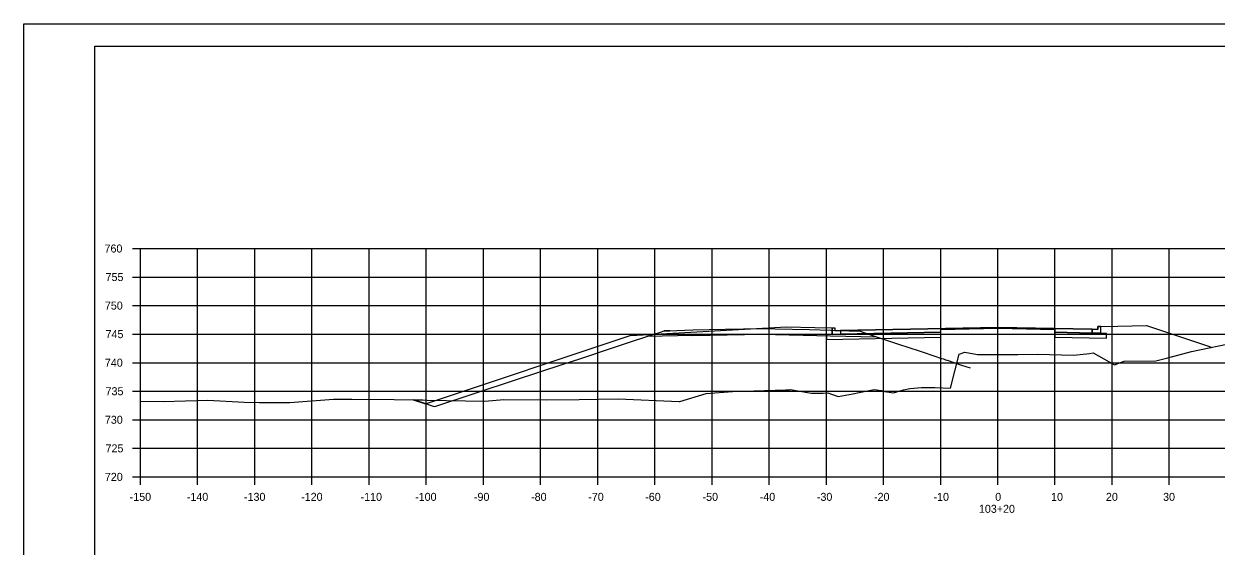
# Model space of a CAD drawing. Extents: x 1202951 to 1376887, y 378065 to 728038.
# Drawn here: x 1374114.6 to 1374323.2, y 378881.8 to 378973.3 of the extents above; entities that cross this region are included whole.
import ezdxf

# ---------------------------------------------------------------- set-up
doc = ezdxf.new("R2010")
doc.units = 0
for name, color, linetype in [('Default', 7, 'Continuous'), ('R_Alt Surface', 7, 'Continuous'), ('R_Axis', 7, 'Continuous'), ('R_Axis Annot', 7, 'Continuous'), ('R_Exist Surface', 7, 'Continuous'), ('R_Fin Surface', 7, 'Continuous'), ('R_Grid', 7, 'Continuous'), ('R_No Plot', 7, 'Continuous'), ('R_Proposed Road', 7, 'Continuous')]:
    doc.layers.add(name, color=color, linetype=linetype)

msp = doc.modelspace()

# ---------------------------------------------------------------- linework, layer by layer
at = {"layer": 'Default'}
for points in [[(1374255.98, 378920.03), (1374256.47, 378920.03), (1374256.48, 378919.53), (1374257.48, 378919.55), (1374257.48, 378918.89), (1374255.98, 378918.86)], [(1374302.98, 378920.25), (1374302.49, 378920.25), (1374302.48, 378919.75), (1374301.48, 378919.77), (1374301.48, 378919.11), (1374302.98, 378919.08)]]:
    msp.add_lwpolyline(points, close=True, dxfattribs=at)
at = {"layer": 'R_Alt Surface'}
for points in [[(1374231.62, 378918.66), (1374243.66, 378918.89), (1374255.71, 378918.63)], [(1374255.98, 378920.03), (1374255.98, 378918.86), (1374257.48, 378918.89), (1374274.98, 378919.24), (1374274.98, 378919.74), (1374284.98, 378919.94), (1374294.98, 378919.74), (1374294.98, 378919.24), (1374301.48, 378919.11), (1374302.98, 378919.08), (1374302.98, 378920.25)], [(1374231.62, 378918.66), (1374223.59, 378918.51)], [(1374255.71, 378918.63), (1374263.75, 378918.46)]]:
    msp.add_lwpolyline(points, dxfattribs=at)
for points in [[(1374257.48, 378918.89), (1374255.98, 378918.86), (1374254.98, 378918.84), (1374254.98, 378918), (1374274.98, 378918.4), (1374274.98, 378919.24)], [(1374257.48, 378919.55), (1374257.48, 378918.89), (1374274.98, 378919.24), (1374274.98, 378919.74), (1374284.98, 378919.94), (1374294.98, 378919.74), (1374294.98, 378919.24), (1374301.48, 378919.11), (1374301.48, 378919.77), (1374301.48, 378919.77), (1374284.98, 378920.1), (1374257.48, 378919.55)], [(1374303.98, 378919.06), (1374302.98, 378919.08), (1374301.48, 378919.11), (1374294.98, 378919.24), (1374294.98, 378918.4), (1374303.98, 378918.22)]]:
    msp.add_lwpolyline(points, close=True, dxfattribs=at)
at = {"layer": 'R_Axis'}
for p, q in [((1374133.58, 378933.92), (1374134.98, 378933.92)), ((1374134.98, 378893.92), (1374134.98, 378933.92)), ((1374133.58, 378928.92), (1374134.98, 378928.92)), ((1374133.58, 378923.92), (1374134.98, 378923.92)), ((1374133.58, 378918.92), (1374134.98, 378918.92)), ((1374133.58, 378913.92), (1374134.98, 378913.92)), ((1374133.58, 378908.92), (1374134.98, 378908.92)), ((1374133.58, 378903.92), (1374134.98, 378903.92)), ((1374133.58, 378898.92), (1374134.98, 378898.92)), ((1374133.58, 378893.92), (1374134.98, 378893.92)), ((1374134.98, 378893.92), (1374434.98, 378893.92)), ((1374134.98, 378892.52), (1374134.98, 378893.92)), ((1374144.98, 378892.52), (1374144.98, 378893.92)), ((1374154.98, 378892.52), (1374154.98, 378893.92)), ((1374164.98, 378892.52), (1374164.98, 378893.92)), ((1374174.98, 378892.52), (1374174.98, 378893.92)), ((1374184.98, 378892.52), (1374184.98, 378893.92)), ((1374194.98, 378892.52), (1374194.98, 378893.92)), ((1374204.98, 378892.52), (1374204.98, 378893.92)), ((1374214.98, 378892.52), (1374214.98, 378893.92)), ((1374224.98, 378892.52), (1374224.98, 378893.92)), ((1374234.98, 378892.52), (1374234.98, 378893.92)), ((1374244.98, 378892.52), (1374244.98, 378893.92)), ((1374254.98, 378892.52), (1374254.98, 378893.92)), ((1374264.98, 378892.52), (1374264.98, 378893.92)), ((1374274.98, 378892.52), (1374274.98, 378893.92)), ((1374284.98, 378892.52), (1374284.98, 378893.92)), ((1374294.98, 378892.52), (1374294.98, 378893.92)), ((1374304.98, 378892.52), (1374304.98, 378893.92)), ((1374314.98, 378892.52), (1374314.98, 378893.92))]:
    msp.add_line(p, q, dxfattribs=at)
at = {"layer": 'R_Exist Surface'}
msp.add_lwpolyline([(1374134.98, 378907.15), (1374138.93, 378907.1), (1374146.74, 378907.35), (1374153.12, 378907), (1374155.78, 378906.94), (1374161.13, 378906.94), (1374168.77, 378907.51), (1374171.95, 378907.54), (1374179.37, 378907.45), (1374183.2, 378907.44), (1374184.38, 378907.44), (1374185.14, 378907.38), (1374195.25, 378907.2), (1374198.54, 378907.45), (1374206.01, 378907.42), (1374211.73, 378907.46), (1374218.53, 378907.56), (1374229.25, 378907.11), (1374229.28, 378907.11), (1374229.35, 378907.13), (1374233.95, 378908.51), (1374238.56, 378908.87), (1374247.91, 378909.18), (1374248.55, 378909.19), (1374248.72, 378909.22), (1374249.64, 378909.02), (1374252.35, 378908.6), (1374254.43, 378908.57), (1374255.22, 378908.61), (1374257.04, 378908), (1374259.61, 378908.44), (1374260.73, 378908.69), (1374263.33, 378909.21), (1374264.58, 378909.07), (1374265.16, 378908.87), (1374266.7, 378908.62), (1374268.49, 378909.18), (1374269.58, 378909.42), (1374271.64, 378909.59), (1374273.97, 378909.59), (1374276.67, 378909.48), (1374278.23, 378915.44), (1374279.18, 378915.75), (1374281.4, 378915.38), (1374288.5, 378915.35), (1374291.84, 378915.41), (1374298.3, 378915.25), (1374301.01, 378915.5), (1374301.65, 378915.65), (1374305.38, 378913.52), (1374306.44, 378913.93), (1374307.07, 378914.21), (1374312.6, 378914.23), (1374314.74, 378914.79), (1374318.85, 378915.87), (1374326.73, 378917.49)], dxfattribs=at)
at = {"layer": 'R_Fin Surface'}
for points in [[(1374182.67, 378907.44), (1374184.83, 378906.72), (1374220.83, 378918.72), (1374221.83, 378918.72), (1374247.98, 378920.19), (1374252.98, 378920.09), (1374255.98, 378920.03), (1374256.47, 378920.03), (1374256.48, 378919.53), (1374257.48, 378919.55), (1374284.98, 378920.1), (1374301.48, 378919.77), (1374302.48, 378919.75), (1374302.49, 378920.25), (1374302.98, 378920.25), (1374305.98, 378920.31), (1374310.98, 378920.41), (1374312.56, 378919.89), (1374320.44, 378917.26), (1374322, 378916.74), (1374322.41, 378916.6)], [(1374182.77, 378907.45), (1374182.94, 378907.39), (1374184.31, 378906.94), (1374186.21, 378906.31), (1374186.48, 378906.22), (1374200.6, 378910.9), (1374208.92, 378913.66), (1374212, 378914.67), (1374217.89, 378916.63), (1374220.91, 378917.63), (1374223.59, 378918.51), (1374225.95, 378919.29), (1374226.6, 378919.51), (1374226.84, 378919.51), (1374227.6, 378919.51), (1374228.8, 378919.55), (1374231.62, 378919.66), (1374237.26, 378919.77), (1374243.66, 378919.89), (1374246.04, 378919.84), (1374252.01, 378919.71), (1374255.71, 378919.63), (1374258.98, 378919.5), (1374259.73, 378919.47), (1374259.95, 378919.47), (1374260.73, 378919.47), (1374262.86, 378918.76), (1374263.75, 378918.46), (1374265.51, 378917.88), (1374267.62, 378917.17), (1374271.19, 378915.99), (1374274.31, 378914.95), (1374274.6, 378914.85), (1374275.11, 378914.68), (1374275.46, 378914.57), (1374275.85, 378914.44), (1374276.07, 378914.37), (1374276.12, 378914.35), (1374278.63, 378913.51), (1374280.12, 378913.01)]]:
    msp.add_lwpolyline(points, dxfattribs=at)
at = {"layer": 'R_Grid'}
for p, q in [((1374134.98, 378933.92), (1374434.98, 378933.92)), ((1374134.98, 378893.92), (1374134.98, 378933.92)), ((1374144.98, 378893.92), (1374144.98, 378933.92)), ((1374154.98, 378893.92), (1374154.98, 378933.92)), ((1374164.98, 378893.92), (1374164.98, 378933.92)), ((1374174.98, 378893.92), (1374174.98, 378933.92)), ((1374184.98, 378893.92), (1374184.98, 378933.92)), ((1374194.98, 378893.92), (1374194.98, 378933.92)), ((1374204.98, 378893.92), (1374204.98, 378933.92)), ((1374214.98, 378893.92), (1374214.98, 378933.92)), ((1374224.98, 378893.92), (1374224.98, 378933.92)), ((1374234.98, 378893.92), (1374234.98, 378933.92)), ((1374244.98, 378893.92), (1374244.98, 378933.92)), ((1374254.98, 378893.92), (1374254.98, 378933.92)), ((1374264.98, 378893.92), (1374264.98, 378933.92)), ((1374274.98, 378893.92), (1374274.98, 378933.92)), ((1374284.98, 378893.92), (1374284.98, 378933.92)), ((1374294.98, 378893.92), (1374294.98, 378933.92)), ((1374304.98, 378893.92), (1374304.98, 378933.92)), ((1374314.98, 378893.92), (1374314.98, 378933.92)), ((1374134.98, 378928.92), (1374434.98, 378928.92)), ((1374134.98, 378923.92), (1374434.98, 378923.92)), ((1374134.98, 378918.92), (1374434.98, 378918.92)), ((1374134.98, 378913.92), (1374434.98, 378913.92)), ((1374134.98, 378908.92), (1374434.98, 378908.92)), ((1374134.98, 378903.92), (1374434.98, 378903.92)), ((1374134.98, 378898.92), (1374434.98, 378898.92)), ((1374134.98, 378893.92), (1374434.98, 378893.92))]:
    msp.add_line(p, q, dxfattribs=at)
at = {"layer": 'R_No Plot'}
for p, q in [((1374114.58, 378973.28), (1374447.91, 378973.28)), ((1374126.98, 378969.38), (1374443.16, 378969.38)), ((1374126.98, 378763.92), (1374126.98, 378969.38)), ((1374279.5, 378969.12), (1374279.5, 378969.12)), ((1374279.5, 378969.12), (1374279.5, 378969.12))]:
    msp.add_line(p, q, dxfattribs=at)
for points in [[(1374114.57, 378973.28), (1374447.91, 378973.28), (1374447.91, 378759.94), (1374114.57, 378759.94)], [(1374360.9, 378969.38), (1374380.52, 378969.38), (1374380.52, 378959.5), (1374396.63, 378959.5), (1374419.83, 378959.5), (1374419.83, 378935.17), (1374443.16, 378935.17), (1374443.16, 378763.92), (1374126.98, 378763.92), (1374126.98, 378969.38)]]:
    msp.add_lwpolyline(points, close=True, dxfattribs=at)
at = {"layer": 'R_Proposed Road'}
for points in [[(1374227.6, 378919.51), (1374226.6, 378919.51)], [(1374259.73, 378919.47), (1374260.73, 378919.47)]]:
    msp.add_lwpolyline(points, dxfattribs=at)

# ---------------------------------------------------------------- texts
at = {"layer": 'R_Axis Annot'}
for s, p in [('760', (1374128.69, 378933.22)), ('755', (1374128.87, 378928.22)), ('750', (1374128.75, 378923.22)), ('745', (1374128.87, 378918.22)), ('740', (1374128.75, 378913.22)), ('735', (1374128.87, 378908.22)), ('730', (1374128.75, 378903.22)), ('725', (1374128.87, 378898.22)), ('720', (1374128.75, 378893.22)), ('-150', (1374133.09, 378889.72)), ('-140', (1374143.09, 378889.72)), ('-130', (1374153.09, 378889.72)), ('-120', (1374163.09, 378889.72)), ('-110', (1374173.49, 378889.72)), ('-100', (1374183.03, 378889.72)), ('-90', (1374193.32, 378889.72)), ('-80', (1374203.32, 378889.72)), ('-70', (1374213.32, 378889.72)), ('-60', (1374223.29, 378889.72)), ('-50', (1374233.32, 378889.72)), ('-40', (1374243.32, 378889.72)), ('-30', (1374253.32, 378889.72)), ('-20', (1374263.32, 378889.72)), ('-10', (1374273.72, 378889.72)), ('0', (1374284.52, 378889.72)), ('10', (1374294.29, 378889.72)), ('20', (1374303.89, 378889.72)), ('30', (1374313.89, 378889.72)), ('103+20', (1374281.67, 378887.62))]:
    msp.add_text(s, height=1.4, dxfattribs=at).set_placement(p)

doc.saveas('drawing.dxf')
